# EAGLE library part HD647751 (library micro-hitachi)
SH7751 Hitachi SuperH RISC engine The SH7751 Series microprocessor, featuring a built-in PCI bus controller compatible with PCs and multimedia devices. Source: Hitachi, Ltd. SH7751_R_V3.0.pdf
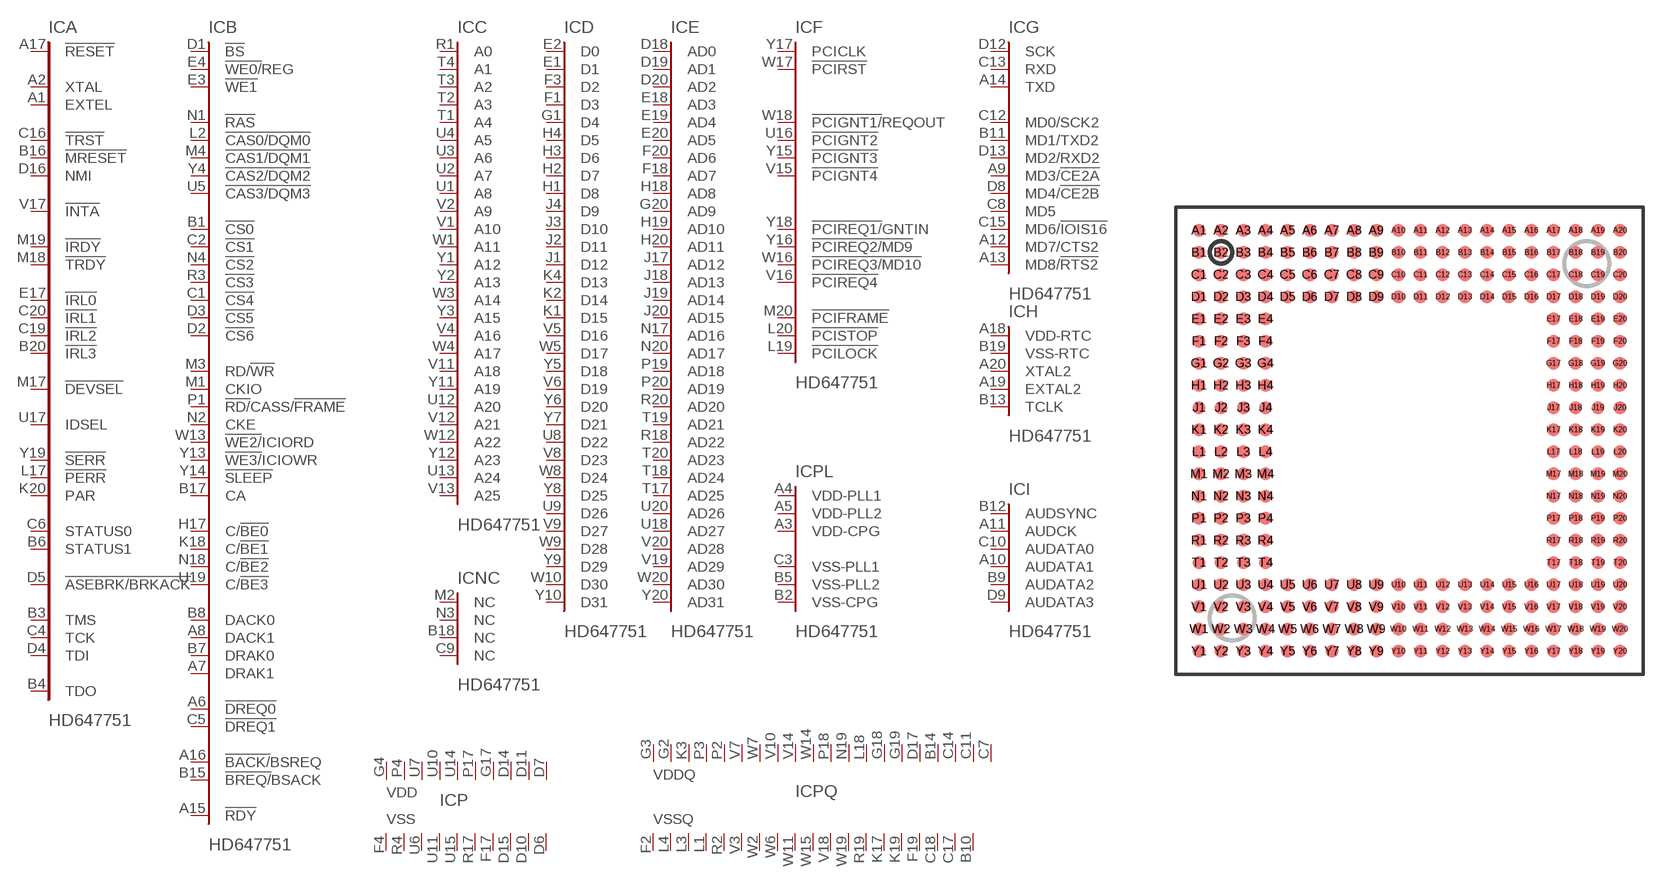
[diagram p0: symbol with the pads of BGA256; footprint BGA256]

Designator prefix IC; gates A=SH7751-S C=SH7751-A D=SH7751-D E=SH7751-AD G=SH7751-SER H=SH7751-RTC I=SH7751-AU P=SH7751-PWR PQ=SH7751-PWRQ PL=SH7751-PLL NC=SH7751-NC B=SH7751-CONTROL F=SH7751-PCI

## HD647751BP167 (OC_FARNELL: unknown; OC_NEWARK: unknown)  [BGA256]
A1  A:EXTEL  in
A2  A:XTAL  out
A3  PL:VDD-CPG  pwr
A4  PL:VDD-PLL1  pwr
A5  PL:VDD-PLL2  pwr
A6  B:!DREQ0  in
A7  B:DRAK1  out
A8  B:DACK1  out
A9  G:MD3/!CE2A
A10  I:AUDATA1  pas
A11  I:AUDCK  pas
A12  G:MD7/CTS2
A13  G:MD8/!RTS2
A14  G:TXD  out
A15  B:!RDY  in
A16  B:!BACK/!BSREQ  out
A17  A:!RESET  in
A18  H:VDD-RTC  pwr
A19  H:EXTAL2  in
A20  H:XTAL2  out
B1  B:!CS0  out
B2  PL:VSS-CPG  pwr
B3  A:TMS  in
B4  A:TDO  out
B5  PL:VSS-PLL2  pwr
B6  A:STATUS1  out
B7  B:DRAK0  out
B8  B:DACK0  out
B9  I:AUDATA2  pas
B10  PQ:VSSQ  pwr
B11  G:MD1/TXD2
B12  I:AUDSYNC  pas
B13  H:TCLK
B14  PQ:VDDQ  pwr
B15  B:!BREQ/!BSACK  in
B16  A:!MRESET  in
B17  B:CA  in
B18  NC:NC  nc
B19  H:VSS-RTC  pwr
B20  A:!IRL3  in
C1  B:!CS4  out
C2  B:!CS1  out
C3  PL:VSS-PLL1  pwr
C4  A:TCK  in
C5  B:!DREQ1  in
C6  A:STATUS0  out
C7  PQ:VDDQ  pwr
C8  G:MD5  in
C9  NC:NC  nc
C10  I:AUDATA0  pas
C11  PQ:VDDQ  pwr
C12  G:MD0/SCK2
C13  G:RXD  in
C14  PQ:VDDQ  pwr
C15  G:MD6/!IOIS16  in
C16  A:!TRST  in
C17  PQ:VSSQ  pwr
C18  PQ:VSSQ  pwr
C19  A:!IRL2  in
C20  A:!IRL1  in
D1  B:!BS  out
D2  B:!CS6  out
D3  B:!CS5  out
D4  A:TDI  in
D5  A:!ASEBRK/BRKACK
D6  P:VSS  pwr
D7  P:VDD  pwr
D8  G:MD4/!CE2B
D9  I:AUDATA3  pas
D10  P:VSS  pwr
D11  P:VDD  pwr
D12  G:SCK
D13  G:MD2/RXD2  in
D14  P:VDD  pwr
D15  P:VSS  pwr
D16  A:NMI  in
D17  PQ:VDDQ  pwr
D18  E:AD0
D19  E:AD1
D20  E:AD2
E1  D:D1
E2  D:D0
E3  B:!WE1  out
E4  B:!WE0/!REG  out
E17  A:!IRL0  in
E18  E:AD3
E19  E:AD4
E20  E:AD5
F1  D:D3
F2  PQ:VSSQ  pwr
F3  D:D2
F4  P:VSS  pwr
F17  P:VSS  pwr
F18  E:AD7
F19  PQ:VSSQ  pwr
F20  E:AD6
G1  D:D4
G2  PQ:VDDQ  pwr
G3  PQ:VDDQ  pwr
G4  P:VDD  pwr
G17  P:VDD  pwr
G18  PQ:VDDQ  pwr
G19  PQ:VDDQ  pwr
G20  E:AD9
H1  D:D8
H2  D:D7
H3  D:D6
H4  D:D5
H17  B:C/!BE0
H18  E:AD8
H19  E:AD10
H20  E:AD11
J1  D:D12
J2  D:D11
J3  D:D10
J4  D:D9
J17  E:AD12
J18  E:AD13
J19  E:AD14
J20  E:AD15
K1  D:D15
K2  D:D14
K3  PQ:VDDQ  pwr
K4  D:D13
K17  PQ:VSSQ  pwr
K18  B:C/!BE1
K19  PQ:VSSQ  pwr
K20  A:PAR
L1  PQ:VSSQ  pwr
L2  B:!CAS0/DQM0  out
L3  PQ:VSSQ  pwr
L4  PQ:VSSQ  pwr
L17  A:!PERR
L18  PQ:VDDQ  pwr
L19  F:!PCILOCK
L20  F:!PCISTOP
M1  B:CKIO  out
M2  NC:NC  nc
M3  B:RD/!WR  out
M4  B:!CAS1/DQM1  out
M17  A:!DEVSEL
M18  A:!TRDY
M19  A:!IRDY
M20  F:!PCIFRAME
N1  B:!RAS  out
N2  B:CKE  out
N3  NC:NC  nc
N4  B:!CS2  out
N17  E:AD16
N18  B:C/!BE2
N19  PQ:VDDQ  pwr
N20  E:AD17
P1  B:!RD/!CASS/!FRAME  out
P2  PQ:VDDQ  pwr
P3  PQ:VDDQ  pwr
P4  P:VDD  pwr
P17  P:VDD  pwr
P18  PQ:VDDQ  pwr
P19  E:AD18
P20  E:AD19
R1  C:A0  out
R2  PQ:VSSQ  pwr
R3  B:!CS3  out
R4  P:VSS  pwr
R17  P:VSS  pwr
R18  E:AD22
R19  PQ:VSSQ  pwr
R20  E:AD20
T1  C:A4  out
T2  C:A3  out
T3  C:A2  out
T4  C:A1  out
T17  E:AD25
T18  E:AD24
T19  E:AD21
T20  E:AD23
U1  C:A8  out
U2  C:A7  out
U3  C:A6  out
U4  C:A5  out
U5  B:!CAS3/DQM3  out
U6  P:VSS  pwr
U7  P:VDD  pwr
U8  D:D22
U9  D:D26
U10  P:VDD  pwr
U11  P:VSS  pwr
U12  C:A20  out
U13  C:A24  out
U14  P:VDD  pwr
U15  P:VSS  pwr
U16  F:!PCIGNT2  out
U17  A:IDSEL  in
U18  E:AD27
U19  B:C/!BE3
U20  E:AD26
V1  C:A10  out
V2  C:A9  out
V3  PQ:VSSQ  pwr
V4  C:A16  out
V5  D:D16
V6  D:D19
V7  PQ:VDDQ  pwr
V8  D:D23
V9  D:D27
V10  PQ:VDDQ  pwr
V11  C:A18  out
V12  C:A21  out
V13  C:A25  out
V14  PQ:VDDQ  pwr
V15  F:!PCIGNT4  out
V16  F:!PCIREQ4  in
V17  A:!INTA  out
V18  PQ:VSSQ  pwr
V19  E:AD29
V20  E:AD28
W1  C:A11  out
W2  PQ:VSSQ  pwr
W3  C:A14  out
W4  C:A17  out
W5  D:D17
W6  PQ:VSSQ  pwr
W7  PQ:VDDQ  pwr
W8  D:D24
W9  D:D28
W10  D:D30
W11  PQ:VSSQ  pwr
W12  C:A22  out
W13  B:!WE2/!ICIORD  out
W14  PQ:VDDQ  pwr
W15  PQ:VSSQ  pwr
W16  F:!PCIREQ3/MD10  in
W17  F:!PCIRST  out
W18  F:!PCIGNT1/!REQOUT  out
W19  PQ:VSSQ  pwr
W20  E:AD30
Y1  C:A12  out
Y2  C:A13  out
Y3  C:A15  out
Y4  B:!CAS2/DQM2  out
Y5  D:D18
Y6  D:D20
Y7  D:D21
Y8  D:D25
Y9  D:D29
Y10  D:D31
Y11  C:A19  out
Y12  C:A23  out
Y13  B:!WE3/!ICIOWR  out
Y14  B:!SLEEP  in
Y15  F:!PCIGNT3  out
Y16  F:!PCIREQ2/MD9  in
Y17  F:PCICLK  in
Y18  F:!PCIREQ1/!GNTIN  in
Y19  A:!SERR
Y20  E:AD31

## HD647751RBP240 (OC_FARNELL: unknown; OC_NEWARK: unknown)  [BGA256]
Pads as for BGA256

## HD647751RBP200 (OC_FARNELL: unknown; OC_NEWARK: unknown)  [BGA256]
Pads as for BGA256

## Footprint BGA256 (pad centres in mm)
256-pin BGA Hitachi Code BP-256 Source: SH7751_R_V3.0.pdf
smd 0.75 x 0.75: A1 -12.065,12.065; A2 -10.795,12.065; A3 -9.525,12.065; A4 -8.255,12.065; A5 -6.985,12.065; A6 -5.715,12.065; A7 -4.445,12.065; A8 -3.175,12.065; A9 -1.905,12.065; A10 -0.635,12.065; A11 0.635,12.065; A12 1.905,12.065; A13 3.175,12.065; A14 4.445,12.065; A15 5.715,12.065; A16 6.985,12.065; A17 8.255,12.065; A18 9.525,12.065; A19 10.795,12.065; A20 12.065,12.065; B1 -12.065,10.795; B2 -10.795,10.795; B3 -9.525,10.795; B4 -8.255,10.795; B5 -6.985,10.795; B6 -5.715,10.795; B7 -4.445,10.795; B8 -3.175,10.795; B9 -1.905,10.795; B10 -0.635,10.795; B11 0.635,10.795; B12 1.905,10.795; B13 3.175,10.795; B14 4.445,10.795; B15 5.715,10.795; B16 6.985,10.795; B17 8.255,10.795; B18 9.525,10.795; B19 10.795,10.795; B20 12.065,10.795; C1 -12.065,9.525; C2 -10.795,9.525; C3 -9.525,9.525; C4 -8.255,9.525; C5 -6.985,9.525; C6 -5.715,9.525; C7 -4.445,9.525; C8 -3.175,9.525; C9 -1.905,9.525; C10 -0.635,9.525; C11 0.635,9.525; C12 1.905,9.525; C13 3.175,9.525; C14 4.445,9.525; C15 5.715,9.525; C16 6.985,9.525; C17 8.255,9.525; C18 9.525,9.525; C19 10.795,9.525; C20 12.065,9.525; D1 -12.065,8.255; D2 -10.795,8.255; D3 -9.525,8.255; D4 -8.255,8.255; D5 -6.985,8.255; D6 -5.715,8.255; D7 -4.445,8.255; D8 -3.175,8.255; D9 -1.905,8.255; D10 -0.635,8.255; D11 0.635,8.255; D12 1.905,8.255; D13 3.175,8.255; D14 4.445,8.255; D15 5.715,8.255; D16 6.985,8.255; D17 8.255,8.255; D18 9.525,8.255; D19 10.795,8.255; D20 12.065,8.255; E1 -12.065,6.985; E2 -10.795,6.985; E3 -9.525,6.985; E4 -8.255,6.985; E17 8.255,6.985; E18 9.525,6.985; E19 10.795,6.985; E20 12.065,6.985; F1 -12.065,5.715; F2 -10.795,5.715; F3 -9.525,5.715; F4 -8.255,5.715; F17 8.255,5.715; F18 9.525,5.715; F19 10.795,5.715; F20 12.065,5.715; G1 -12.065,4.445; G2 -10.795,4.445; G3 -9.525,4.445; G4 -8.255,4.445; G17 8.255,4.445; G18 9.525,4.445; G19 10.795,4.445; G20 12.065,4.445; H1 -12.065,3.175; H2 -10.795,3.175; H3 -9.525,3.175; H4 -8.255,3.175; H17 8.255,3.175; H18 9.525,3.175; H19 10.795,3.175; H20 12.065,3.175; J1 -12.065,1.905; J2 -10.795,1.905; J3 -9.525,1.905; J4 -8.255,1.905; J17 8.255,1.905; J18 9.525,1.905; J19 10.795,1.905; J20 12.065,1.905; K1 -12.065,0.635; K2 -10.795,0.635; K3 -9.525,0.635; K4 -8.255,0.635; K17 8.255,0.635; K18 9.525,0.635; K19 10.795,0.635; K20 12.065,0.635; L1 -12.065,-0.635; L2 -10.795,-0.635; L3 -9.525,-0.635; L4 -8.255,-0.635; L17 8.255,-0.635; L18 9.525,-0.635; L19 10.795,-0.635; L20 12.065,-0.635; M1 -12.065,-1.905; M2 -10.795,-1.905; M3 -9.525,-1.905; M4 -8.255,-1.905; M17 8.255,-1.905; M18 9.525,-1.905; M19 10.795,-1.905; M20 12.065,-1.905; N1 -12.065,-3.175; N2 -10.795,-3.175; N3 -9.525,-3.175; N4 -8.255,-3.175; N17 8.255,-3.175; N18 9.525,-3.175; N19 10.795,-3.175; N20 12.065,-3.175; P1 -12.065,-4.445; P2 -10.795,-4.445; P3 -9.525,-4.445; P4 -8.255,-4.445; P17 8.255,-4.445; P18 9.525,-4.445; P19 10.795,-4.445; P20 12.065,-4.445; R1 -12.065,-5.715; R2 -10.795,-5.715; R3 -9.525,-5.715; R4 -8.255,-5.715; R17 8.255,-5.715; R18 9.525,-5.715; R19 10.795,-5.715; R20 12.065,-5.715; T1 -12.065,-6.985; T2 -10.795,-6.985; T3 -9.525,-6.985; T4 -8.255,-6.985; T17 8.255,-6.985; T18 9.525,-6.985; T19 10.795,-6.985; T20 12.065,-6.985; U1 -12.065,-8.255; U2 -10.795,-8.255; U3 -9.525,-8.255; U4 -8.255,-8.255; U5 -6.985,-8.255; U6 -5.715,-8.255; U7 -4.445,-8.255; U8 -3.175,-8.255; U9 -1.905,-8.255; U10 -0.635,-8.255; U11 0.635,-8.255; U12 1.905,-8.255; U13 3.175,-8.255; U14 4.445,-8.255; U15 5.715,-8.255; U16 6.985,-8.255; U17 8.255,-8.255; U18 9.525,-8.255; U19 10.795,-8.255; U20 12.065,-8.255; V1 -12.065,-9.525; V2 -10.795,-9.525; V3 -9.525,-9.525; V4 -8.255,-9.525; V5 -6.985,-9.525; V6 -5.715,-9.525; V7 -4.445,-9.525; V8 -3.175,-9.525; V9 -1.905,-9.525; V10 -0.635,-9.525; V11 0.635,-9.525; V12 1.905,-9.525; V13 3.175,-9.525; V14 4.445,-9.525; V15 5.715,-9.525; V16 6.985,-9.525; V17 8.255,-9.525; V18 9.525,-9.525; V19 10.795,-9.525; V20 12.065,-9.525; W1 -12.065,-10.795; W2 -10.795,-10.795; W3 -9.525,-10.795; W4 -8.255,-10.795; W5 -6.985,-10.795; W6 -5.715,-10.795; W7 -4.445,-10.795; W8 -3.175,-10.795; W9 -1.905,-10.795; W10 -0.635,-10.795; W11 0.635,-10.795; W12 1.905,-10.795; W13 3.175,-10.795; W14 4.445,-10.795; W15 5.715,-10.795; W16 6.985,-10.795; W17 8.255,-10.795; W18 9.525,-10.795; W19 10.795,-10.795; W20 12.065,-10.795; Y1 -12.065,-12.065; Y2 -10.795,-12.065; Y3 -9.525,-12.065; Y4 -8.255,-12.065; Y5 -6.985,-12.065; Y6 -5.715,-12.065; Y7 -4.445,-12.065; Y8 -3.175,-12.065; Y9 -1.905,-12.065; Y10 -0.635,-12.065; Y11 0.635,-12.065; Y12 1.905,-12.065; Y13 3.175,-12.065; Y14 4.445,-12.065; Y15 5.715,-12.065; Y16 6.985,-12.065; Y17 8.255,-12.065; Y18 9.525,-12.065; Y19 10.795,-12.065; Y20 12.065,-12.065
